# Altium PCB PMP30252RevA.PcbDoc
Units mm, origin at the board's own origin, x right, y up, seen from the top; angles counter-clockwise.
Board outline 62.23 x 46.99 mm, 2 copper layers (Top Layer, Bottom Layer), stack 1.575 mm thick; 70 components, 32 nets, 163 pads, 35 vias.
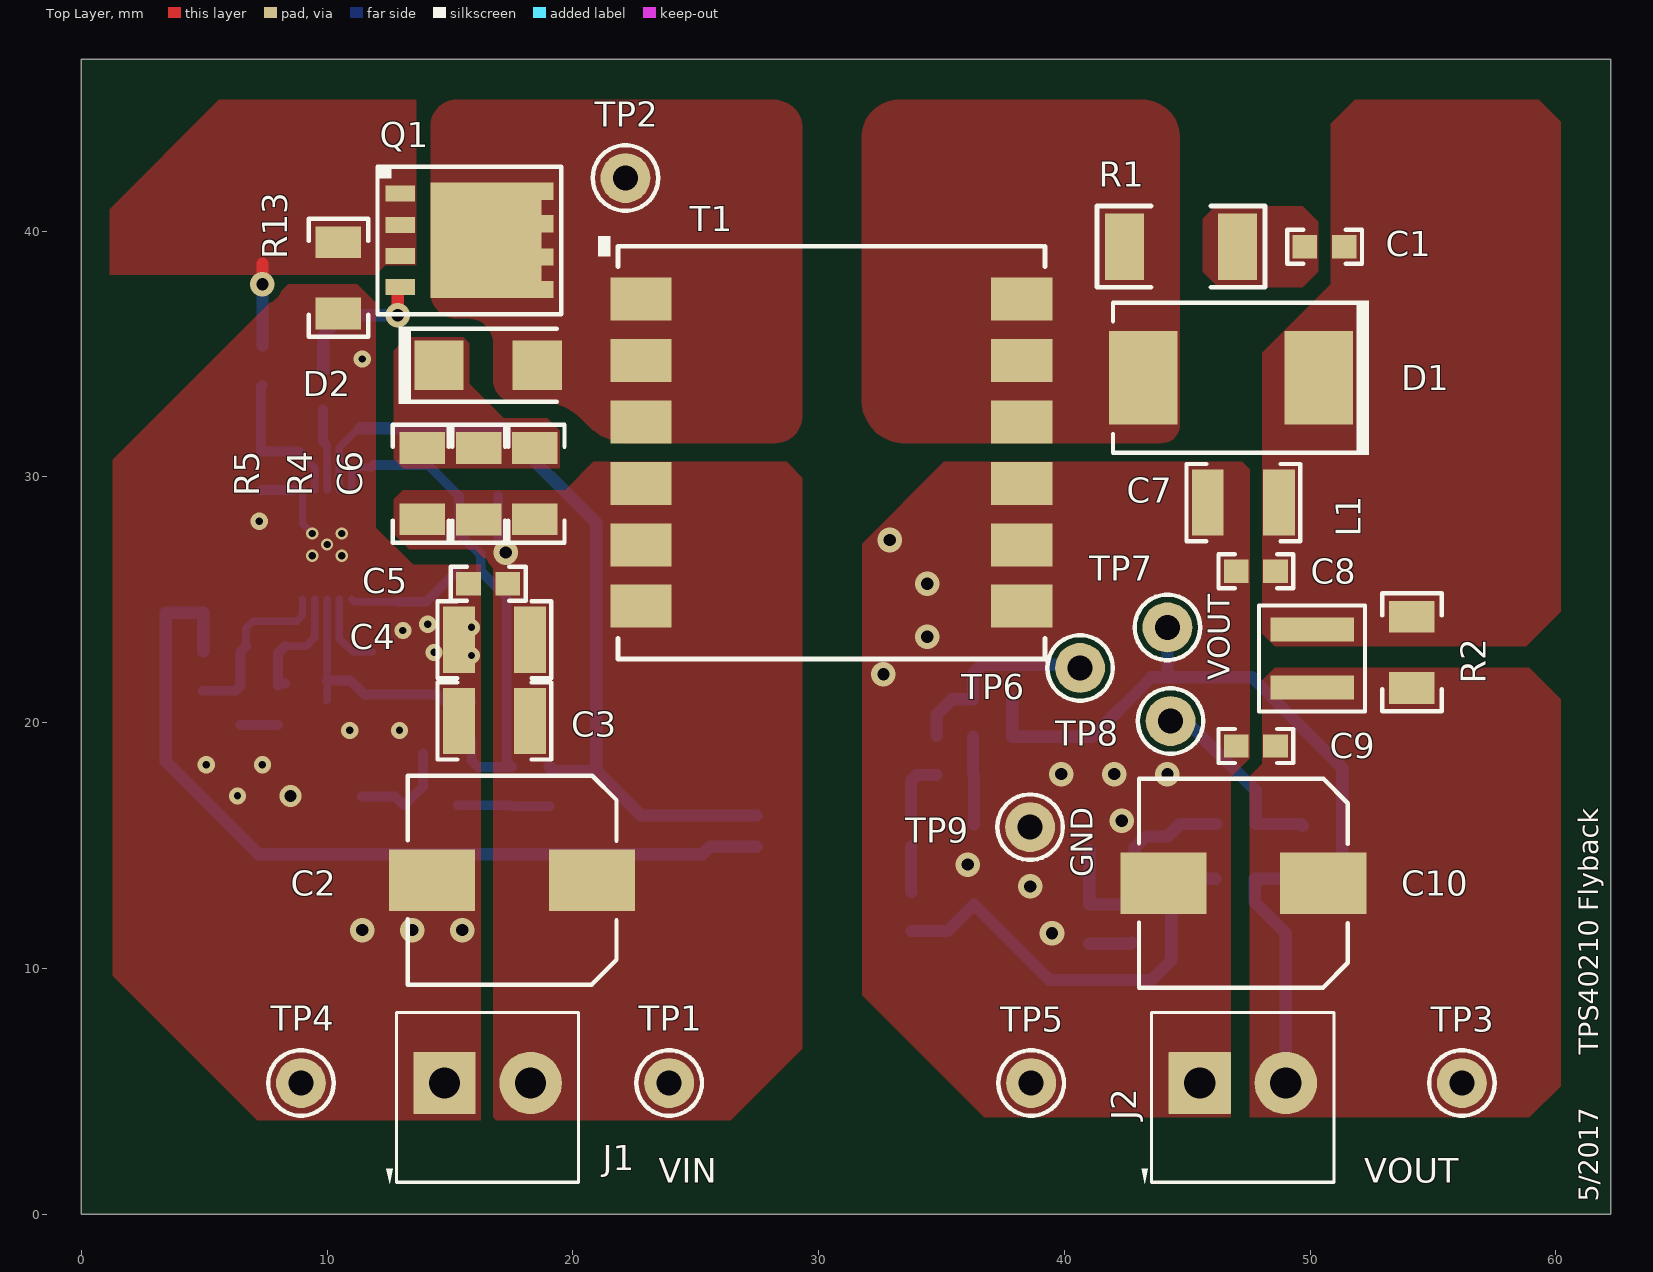
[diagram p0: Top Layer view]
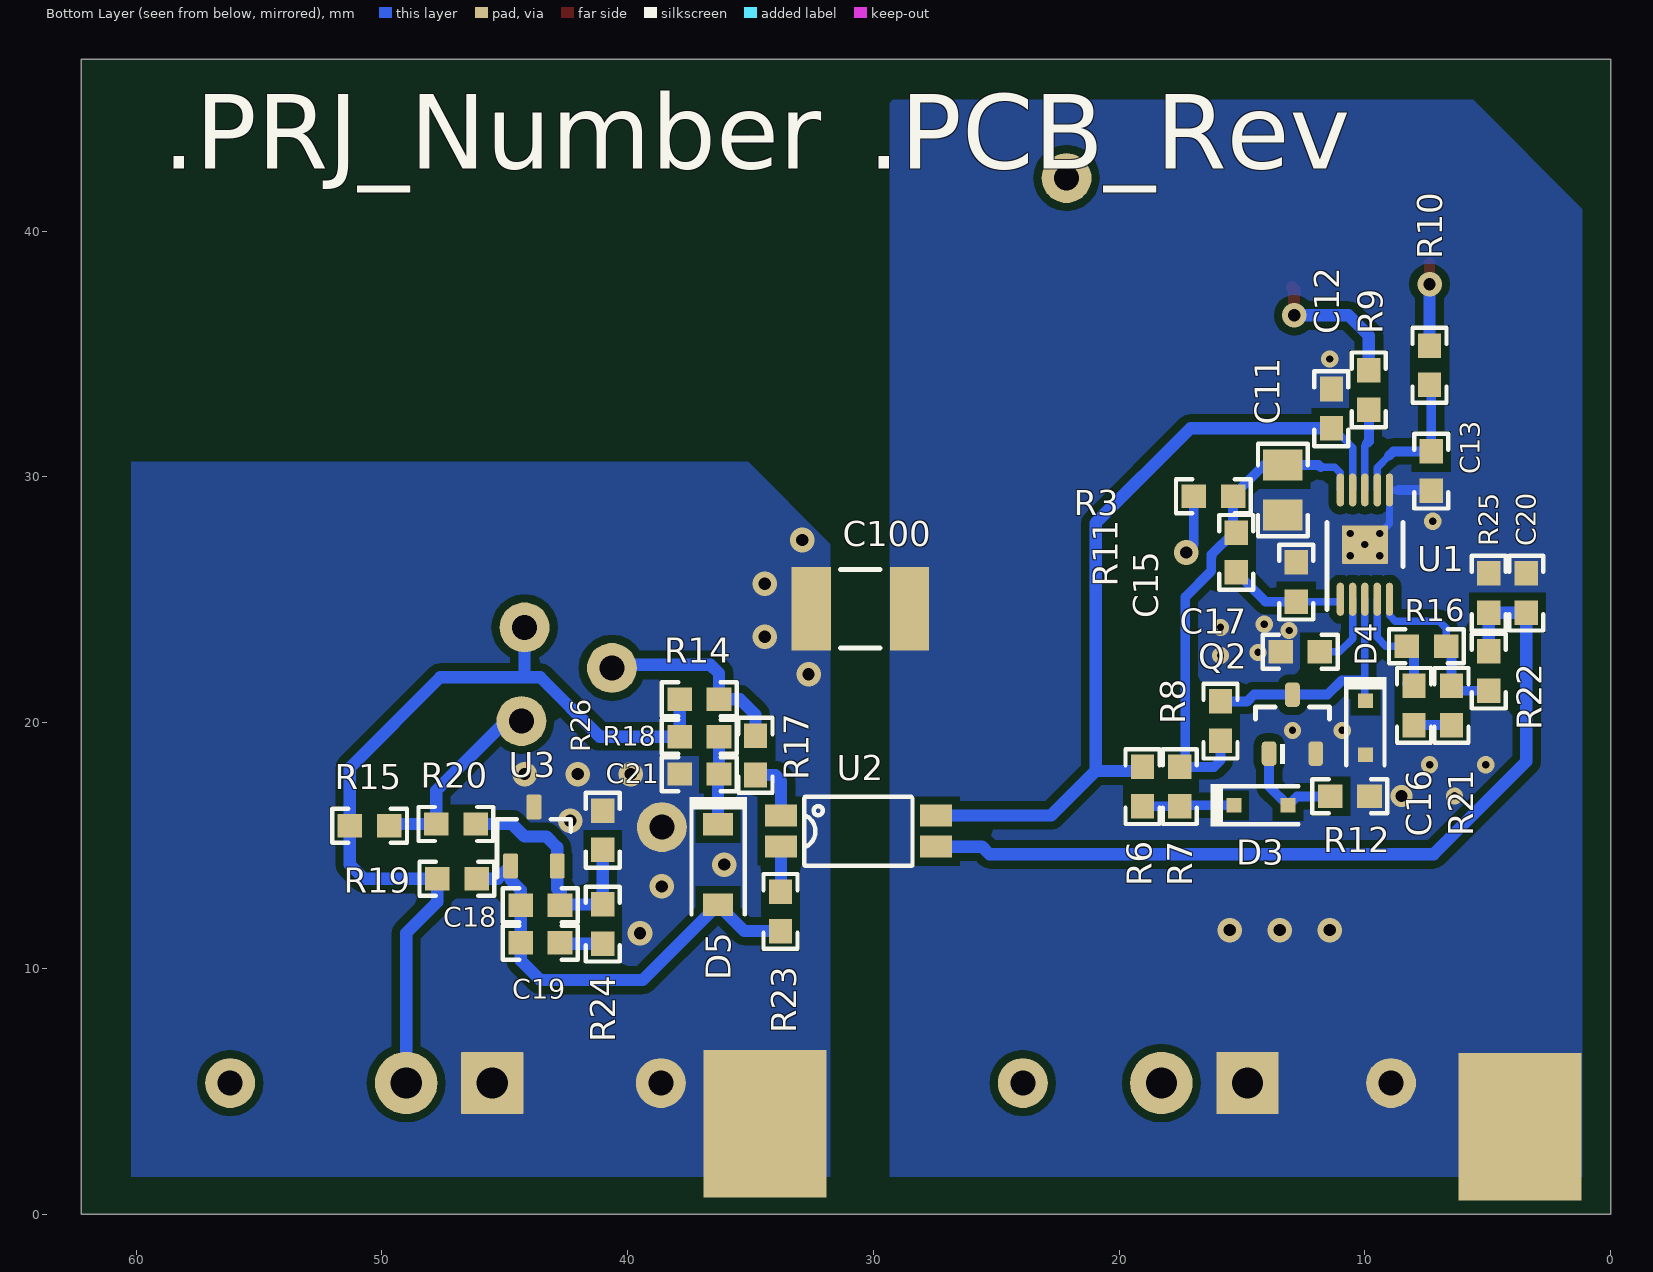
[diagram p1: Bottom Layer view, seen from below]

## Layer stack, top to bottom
Top Solder: solder mask 0.0102, Solder Resist, Dk 3.5
Top Layer: signal copper 0.0356
Dielectric1: core 1.5037, FR-4, Dk 4.8
Bottom Layer: signal copper 0.0356
Bottom Solder: solder mask 0.0102, Solder Resist, Dk 3.5

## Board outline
0,0 62.23,0 62.23,46.99 0,46.99

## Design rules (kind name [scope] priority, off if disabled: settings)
AcuteAngle [All] p1: minimum=4.50000000000000E+0001 checktracksonly=FALSE
AssemblyTestPointUsage [All] p1: valid=2
BoardOutlineClearance BoardOutlineClearance_MountingHoles [OnCopper and InComponentClass('Mounting Holes')] p1: gap=1.016
BoardOutlineClearance BoardOutlineClearance_Poly [OnCopper and InPoly] p2: gap=0.635
BoardOutlineClearance [OnCopper and Not InComponentClass('Logo') and not InComponentClass('FiducialMark') and not InRegion(1000,500,4000,800)] p3: gap=0.5
Clearance Clearance_Keepouts [((IsTrack Or IsArc) And Not InPoly) And IsFree and IsKeepOut vs ((IsTrack Or IsArc) And Not InPoly) And IsFree and IsKeepOut] p1: gap=0
Clearance Clearance_Poly [InPolygon] p2: gap=0.32
Clearance [All] p3: gap=0.32
ComponentClearance ComponentClearance_MountingHoles_FiducialMarks [InComponentClass('Mounting Holes') vs InComponentClass('FiducialMark')] p1: gap=1.27 collisioncheckmode=3 verticalgap=0.254 showdistances=FALSE
ComponentClearance ComponentClearance_Shunt [InComponentClass('Header') vs InComponentClass('Shunt')] p2: gap=0 collisioncheckmode=3 verticalgap=0 showdistances=FALSE
ComponentClearance ComponentClearance_Logo [InComponentClass('Logo')] p3: gap=1.27 collisioncheckmode=3 verticalgap=0.254 showdistances=FALSE
ComponentClearance ComponentClearance_ScrewToNut [(HasFootprint('NY PMS 440 0025 PH')) vs (HasFootprint('Keystone_1902C'))] p4: gap=0.127 collisioncheckmode=3 verticalgap=0.254 showdistances=FALSE
ComponentClearance ComponentClearance_MountingHoles [InComponentClass('Mounting Holes')] p5: gap=6.35 collisioncheckmode=3 verticalgap=2540 showdistances=FALSE
ComponentClearance ComponentClearance_SmallPassives [HasFootprint('0201*') or HasFootprint('0402*') or HasFootprint('0508') or HasFootprint('0603*') or HasFootprint('0612') or HasFootprint('0805*') or HasFootprint('0815*') or HasFootprint('0830*') or HasFootprint('1206*') or HasFootprint('1210*') or HasFootprint('1808*') or HasFootprint('1812*') or HasFootprint('1825*') or HasFootprint('2010*') or HasFootprint('2220*') or HasFootprint('2225*') or HasFootprint('2512*') or HasFootprint('2728*') or HasFootprint('3518*') vs HasFootprint('0201*') or HasFootprint('0402*') or HasFootprint('0508') or HasFootprint('0603*') or HasFootprint('0612') or HasFootprint('0805*') or HasFootprint('0815*') or HasFootprint('0830*') or HasFootprint('1206*') or HasFootprint('1210*') or HasFootprint('1808*') or HasFootprint('1812*') or HasFootprint('1825*') or HasFootprint('2010*') or HasFootprint('2220*') or HasFootprint('2225*') or HasFootprint('2512*') or HasFootprint('2728*') or HasFootprint('3518*')] p6: gap=0.38 collisioncheckmode=3 verticalgap=0.254 showdistances=FALSE
ComponentClearance ComponentClearance_THtoSMT [IsThruComponent vs IsSMTComponent] p7: gap=1.016 collisioncheckmode=3 verticalgap=0.762 showdistances=FALSE
ComponentClearance ComponentClearance_THtoTH [IsThruComponent vs IsThruComponent] p8: gap=0.762 collisioncheckmode=3 verticalgap=0.762 showdistances=FALSE
ComponentClearance [All] p9: gap=0.762 collisioncheckmode=3 verticalgap=0.254 showdistances=FALSE
DiffPairsRouting [All] p1: maxlimit=2.54 minlimit=0.254 mostfreqgap=0.254 toplayer_minwidth=0.381 toplayer_maxwidth=0.381 toplayer_prefwidth=0.381 bottomlayer_minwidth=0.381 bottomlayer_maxwidth=0.381 bottomlayer_prefwidth=0.381 maxuncoupledlength=25.4
FabricationTestPointUsage TestPointUsage [All] p1: valid=2 allowmultiple=FALSE
FabricationTestpoint Testpoint [All] p1: side=3 testpointundercomponent=TRUE minsize=1.016 maxsize=2.54 preferedsize=1.524 minholesize=0 maxholesize=1.016 preferedholesize=0.813 testpointgrid=0.025 allowsidetop=TRUE allowsidebottom=TRUE usegrid=TRUE gridtolerance=0
FanoutControl Fanout_LCC [IsLCC] p1: bgadir=Out bgaviamode=Centered fanoutstyle=Auto fanoutdirection=Alternating viagrid=0.025 // Fanout_LCC (Default Rule)
FanoutControl Fanout_BGA [IsBGA] p2: bgadir=Out bgaviamode=Centered fanoutstyle=Auto fanoutdirection=Alternating viagrid=0.025 // Fanout_BGA (Default Rule)
FanoutControl Fanout_Default [All] p4: bgadir=Out bgaviamode=Centered fanoutstyle=Auto fanoutdirection=Alternating viagrid=0.025 // Fanout_Default (Default Rule)
FanoutControl Fanout_Small [(CompPinCount < 5)] p5: bgadir=Out bgaviamode=Centered fanoutstyle=Auto fanoutdirection=OutThenIn viagrid=0.025 // Fanout_Small (Default Rule)
HoleSize [All] p1: absolutevalues=TRUE maxlimit=6.375 minlimit=0.3 maxpercent=80.000 minpercent=20.000
MinimumAnnularRing MinimumAnnularRing_ThermalPadVias [IsVia and InAnyComponent] p1: minimumring=0.15
MinimumAnnularRing [All] p2: minimumring=0.2
MinimumSolderMaskSliver MinimumSolderMaskSliver_Logo [InComponentClass('Logo') vs InComponentClass('Logo')] p1: minsoldermaskwidth=0.018
MinimumSolderMaskSliver [All] p2: minsoldermaskwidth=0.1
PlaneConnect [All] p1: planeconnectstyle=Relief reliefexpansion=0.254 reliefentries=4 reliefconductorwidth=0.254 reliefairgap=0.254
PolygonConnect [All] p1: connectstyle=Direct reliefconductorwidth=0.254 reliefentries=4 polygonreliefangle="90 Angle" airgapwidth=0.254
RoutingVias ThermalPadVias [IsVia and InAnyComponent] p1: holewidth=0.3 width=0.7 viastyle="Through Hole" minholewidth=0.3 minwidth=0.6 maxholewidth=0.5 maxwidth=1
RoutingVias [All] p2: holewidth=0.5 width=0.9 viastyle="Through Hole" minholewidth=0.3 minwidth=0.6 maxholewidth=1 maxwidth=1.8
SilkToBoardRegionClearance [Not ((IsComment or IsDesignator) And (Hide <> 'False')) and not InRegion(1000,500,4000,800)] p1:
SilkToSilkClearance SilkToSilkClearance_Pb-FreeLogo [(HasFootprint('Pb-Free_Overlay_Medium') OR HasFootprint('Pb-Free_Overlay_Small')) vs (HasFootprint('Pb-Free_Overlay_Medium') OR HasFootprint('Pb-Free_Overlay_Small'))] p1: silktosilkclearance=0
SilkToSilkClearance [All] p2: silktosilkclearance=0.102
SilkToSolderMaskClearance SilkToComponentPadClearance [IsPad and InAnycomponent] p1: minsilkscreentomaskgap=0.127 clearancetoexposedcopper=TRUE
SilkToSolderMaskClearance "Silk to Solder Mask Opening" [All] p2: minsilkscreentomaskgap=0.102 clearancetoexposedcopper=FALSE
SolderMaskExpansion [All] p1: expansion=0.05
Width [All] p1: maxlimit=2.54 minlimit=0.152 preferedwidth=0.254 checkconnectedcopper=TRUE
15 further rules are at their usual default settings.

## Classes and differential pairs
net class U3_Nets: GND2 NetC18_1 NetC18_2
net class U2_Nets: NetC20_1 NetR17_1 NetR23_2 VBP
net class U1_Nets: GND NetC11_1 NetC13_1 NetC15_1 NetC16_1 NetC17_1 NetD4_1 NetR9_1 NetR16_1 VBP
net class TP9_Nets: GND2
net class TP8_Nets: NetR15_2
net class TP7_Nets: VOUT
net class TP6_Nets: NetR14_1
net class TP5_Nets: GND2
net class TP4_Nets: GND
net class TP3_Nets: VOUT
net class TP2_Nets: NetD2_2
net class TP1_Nets: NetC2_1
net class T1_Nets: GND2 NetC2_1 NetD1_2 NetD2_2
net class R26_Nets: GND2 NetC18_1
net class R25_Nets: GND NetC20_1
net class R24_Nets: NetC18_1 NetC19_1
net class R23_Nets: NetC18_2 NetR23_2
net class R22_Nets: NetC20_1 NetR16_1
net class R21_Nets: NetC16_2 NetR16_1
net class R20_Nets: NetC18_1 NetR15_2
net class R19_Nets: NetC18_2 VOUT
net class R18_Nets: NetC21_1 VOUT
net class R17_Nets: NetR14_1 NetR17_1
net class R16_Nets: NetC16_1 NetR16_1
net class R15_Nets: NetR15_2 VOUT
net class R14_Nets: NetR14_1 VOUT
net class R13_Nets: GND NetQ1_1
net class R12_Nets: GND NetD3_2
net class R11_Nets: NetC11_1 NetC15_1
net class R10_Nets: NetC13_1 NetQ1_1
net class R9_Nets: NetQ1_4 NetR9_1
net class R8_Nets: NetC11_1 NetD4_1
net class R7_Nets: NetC11_1 NetD3_1
net class R6_Nets: NetD3_1 VBP
net class R5_Nets: NetC2_1 NetC6_2
net class R4_Nets: NetC2_1 NetC6_2
net class R3_Nets: NetC2_1 NetC11_1
net class R2_Nets: NetC1_1 VOUT
net class R1_Nets: NetC1_2 NetD1_2
net class Q2_Nets: GND NetD3_2 NetD4_1
net class Q1_Nets: NetD2_2 NetQ1_1 NetQ1_4
net class L1_Nets: NetC1_1 VOUT
net class J2_Nets: GND2 VOUT
net class J1_Nets: GND NetC2_1
net class D5_Nets: NetC18_2 NetC21_1
net class D4_Nets: GND NetD4_1
net class D3_Nets: NetD3_1 NetD3_2
net class D2_Nets: NetC6_2 NetD2_2
net class D1_Nets: NetC1_1 NetD1_2
net class C100_Nets: GND GND2
net class C21_Nets: GND2 NetC21_1
net class C20_Nets: GND NetC20_1
net class C19_Nets: NetC18_2 NetC19_1
net class C18_Nets: NetC18_1 NetC18_2
net class C17_Nets: GND NetC17_1
net class C16_Nets: NetC16_1 NetC16_2
net class C15_Nets: GND NetC15_1
net class C13_Nets: GND NetC13_1
net class C12_Nets: GND VBP
net class C11_Nets: GND NetC11_1
net class C10_Nets: GND2 VOUT
net class C9_Nets: GND2 VOUT
net class C8_Nets: GND2 NetC1_1
net class C7_Nets: GND2 NetC1_1
net class C6_Nets: NetC2_1 NetC6_2
net class C5_Nets: GND NetC2_1
net class C4_Nets: GND NetC2_1
net class C3_Nets: GND NetC2_1
net class C2_Nets: GND NetC2_1
net class C1_Nets: NetC1_1 NetC1_2

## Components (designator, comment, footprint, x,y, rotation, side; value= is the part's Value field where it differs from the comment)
C1 "GRM188R72A222KA01D" 0603 50.589,39.37 r180 top
C2 "EEHZC1H680P" SM_RADIAL_8MM 17.526,13.589 r180 top
C3 "GRM32ER71H106KA12L" 1210_270 16.807,20.066 r180 top
C4 "GRM32ER71H106KA12L" 1210_270 16.807,23.368 r180 top
C5 "GCM188R71H104KA57D" 0603 16.553,25.654 r180 top
C6 "GRM319R72A104KA01D" 1206 18.448,29.726 r90 top
C7 "GRM32ER71E226KE15L" 1210_270 47.287,28.956 r180 top
C8 "GCM188R71H104KA57D" 0603 47.795,26.162 r180 top
C9 "GCM188R71H104KA57D" 0603 47.795,19.05 r180 top
C10 "EEHZC1E221P" SM_RADIAL_8MM 47.287,13.462 r180 top
C11 "GRM219R71H334KA88D" 0805_HV 13.335,29.464 r270 bottom
C12 "GRM188R71C105KA12D" 0603 11.36,32.777 r90 bottom
C13 "GRM188R71H221KA01D" 0603 7.296,30.237 r270 bottom
C15 "GRM1885C1H471JA01D" 0603 12.792,25.723 r90 bottom
C16 "GRM188R71H103KA01D" 0603 8.001,20.701 r270 bottom
C17 "GCM188R71H104KA57D" 0603 12.63,22.879 r0 bottom
C18 "GRM1885C1H330JA01D" 0603 43.553,12.565 r0 bottom
C19 "GRM188R71H102KA01D" 0603 43.553,11.041 r0 bottom
C20 "GRM188R71H332KA01D" 0603 3.429,25.273 r90 bottom
C21 "GRM188R71C105KA12D" 0603 37.084,17.907 r0 bottom
C100 "1812GC472KA1" 1812 30.531,24.638 r180 bottom
D1 "B380-13-F" SMC 46.779,34.036 r180 top
D2 "ES1B-13-F" SMA 16.553,34.544 r0 top
D3 "MMSZ5237BS-7-F" SOD-323 14.224,16.637 r180 bottom
D4 "MMSZ5235BS-7-F" sod-323 9.976,19.793 r270 bottom
D5 "MMSD914" SOD-123 36.322,14.224 r270 bottom
J1 "ED555/2DS" TERM_BLK_ED555-2DS 14.775,5.334 r0 top
J2 "ED555/2DS" TERM_BLK_ED555-2DS 45.509,5.334 r0 top
L1 "XFL4020-332MEB" XFL4020 50.081,22.606 r270 top
Q1 "BSC340N08NS3 G" PG-TDSON-8 15.791,39.624 r0 top
Q2 "MMBT2222A" SOT-23 12.946,19.939 r90 bottom
R1 "CRCW201022R0JNEF" 2010 44.747,39.37 r0 top
R2 "CRCW12065R60JNEA" 1206 54.145,22.86 r270 top
R3 "CRCW060310R0FKEA" 0603 16.162,29.218 r0 bottom
R4 "CRCW120639K0JNEA" 1206 16.162,29.718 r270 top
R5 "CRCW120639K0JNEA" 1206 13.876,29.726 r270 top
R6 "CRCW0603100KFKEA" 0603 19.05,17.399 r90 bottom
R7 "CRCW060340K2FKEA" 0603 17.526,17.399 r90 bottom
R8 "CRCW060340K2FKEA" 0603 15.875,20.066 r270 bottom
R9 "CRCW06033R32FKEA" 0603 9.836,33.539 r90 bottom
R10 "CRCW06031K00FKEA" 0603 7.366,34.544 r90 bottom
R11 "CRCW0603287KFKEA" 0603 15.24,26.924 r90 bottom
R12 "CRCW0603100KFKEA" 0603 10.611,16.999 r0 bottom
R13 "WSLP1206R0150FEA" 1206 10.457,38.1 r90 top
R14 "CRCW060349R9FKEA" 0603 37.084,20.955 r0 bottom
R15 "CRCW060349R9FKEA" 0603 50.505,15.806 r180 bottom
R16 "CRCW060330K1FKEA" 0603 7.493,23.114 r0 bottom
R17 "CRCW06032K00FKEA" 0603 34.798,18.669 r90 bottom
R18 "CRCW060320K0FKEA" 0603 37.084,19.431 r0 bottom
R19 "CRCW06032K00FKEA" 0603 46.949,13.647 r0 bottom
R20 "CRCW060320K0FKEA" 0603 46.99,15.875 r0 bottom
R21 "CRCW06035K11FKEA" 0603 6.477,20.701 r270 bottom
R22 "CRCW060310K0FKEA" 0603 4.953,22.098 r90 bottom
R23 "CRCW06030000Z0EA" 0603 33.782,12.319 r90 bottom
R24 "CRCW060340K2FKEA" 0603 41.013,11.803 r270 bottom
R25 "CRCW06031K00FKEA" 0603 4.953,25.273 r270 bottom
R26 "CRCW06035K23FKEA" 0603 41.021,15.621 r270 bottom
T1 "749196241" WURTH_749196211 30.523,30.988 r0 top
TP1 "5000" Keystone5000 23.919,5.334 r180 top
TP2 "5002" Keystone5002 22.141,42.164 r90 top
TP3 "5000" Keystone5000 56.177,5.334 r90 top
TP4 "5001" Keystone5001 8.933,5.334 r180 top
TP5 "5001" Keystone5001 38.651,5.334 r90 top
TP6 "5003" Keystone5003 40.64,22.225 r90 top
TP7 "5000" Keystone5000 44.196,23.876 r90 top
TP8 "5003" Keystone5003 44.323,20.066 r90 top
TP9 "5001" Keystone5001 38.608,15.748 r90 top
U1 "TPS40210" DGQ0010D_N 9.998,27.247 r90 bottom
U2 "TCMT1107" SOP-4 30.607,15.588 r180 bottom
U3 "TL431" DBZ0003A_N 43.815,15.367 r90 bottom

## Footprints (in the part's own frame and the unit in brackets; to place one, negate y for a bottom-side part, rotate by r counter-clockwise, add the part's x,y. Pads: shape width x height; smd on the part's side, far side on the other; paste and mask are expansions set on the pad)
0603 [mm] "0603 from SM-752 data"
  rect 1x0.95 smd: 1(-0.8,0) 2(0.8,0)
  silkscreen extent -1.52,-0.69 1.52,0.69, body extent -0.87,-0.47 0.87,0.47, height 1
0805_HV [mil] "0805 with 30mil clearance between pads"
  rect 50x63 smd: 1(-40,0) 2(40,0)
  silkscreen extent -74,-40 74,40, body extent -43,-29 43,29, height 57
1206 [mm] "1206 from SM-752 data"
  rect 1.3x1.85 smd: 1(-1.45,0) 2(1.45,0)
  silkscreen extent -2.4,-1.21 2.4,1.21, body extent -1.7,-0.9 1.7,0.9, height 1.35
1210_270 [mm] "1210"
  rect 1.3x2.7 smd: 1(-1.45,0) 2(1.45,0)
  silkscreen extent -2.32,-1.57 2.32,1.57, body extent -1.7,-1.35 1.7,1.35, height 2.7
1812 [mm]
  rect 1.6x3.4 smd: 1(-2,0) 2(2,0)
  silkscreen extent -0.8,-1.6 0.8,1.6, body extent -2.4,-1.7 2.4,1.7, height 1.35
2010 [mm] "Chip Capacitor, Body 5.08x2.54mm, IPC Medium Density"
  rect 1.6x2.7 smd: 1(-2.3,0) 2(2.3,0)
  silkscreen extent -3.42,-1.65 3.42,1.65, body extent -2.73,-1.45 2.73,1.45, height 1.66
DBZ0003A_N [mm] "SOT23, 3-Leads, Body 2.9x1.3mm, Pitch 0.95mm, Lead Span 2.4mm, IPC Medium Density"
  rrect17% 1x0.6 smd: 1(-1.2,0.95) 2(-1.2,-0.95) 3(1.2,0)
  silkscreen extent -1.65,-1.5 0.7,1.5, body extent -1.26,-1.46 1.26,1.46, height 0.98
DGQ0010D_N [mm] "TSSOP, 10-Leads, Body 3x3mm, Pitch 0.5mm, Thermal Pad 1.88x1.57mm, IPC Medium Density"
  rrect100% 1.35x0.3 smd: 1(-2.225,1) 2(-2.225,0.5) 3(-2.225,0) 4(-2.225,-0.5) 5(-2.225,-1) 6(2.225,-1) 7(2.225,-0.5) 8(2.225,0) 9(2.225,0.5) 10(2.225,1)
  rrect6% 1.57x1.88 smd: 11(0,0)
  silkscreen extent -2.65,-1.55 0.9,1.55, body extent -2.46,-1.5 2.46,1.5, height 1.1
Keystone5000 [mil] "For Keystone 500x miniature loop terminals"
  round 80 hole 40: 1(0,0)
  silkscreen extent -52,-52 52,52, body extent -49,-49 49,49, height 182
Keystone5001 [mil] "For Keystone 500x miniature loop terminals"
  round 80 hole 40: 1(0,0)
  silkscreen extent -52,-52 52,52, body extent -49,-49 49,49, height 182
Keystone5002 [mil] "For Keystone 500x miniature loop terminals"
  round 80 hole 40: 1(0,0)
  silkscreen extent -52,-52 52,52, body extent -49,-49 49,49, height 182
Keystone5003 [mil] "For Keystone 500x miniature loop terminals"
  round 80 hole 40: 1(0,0)
  silkscreen extent -52,-52 52,52, body extent -49,-49 49,49, height 182
PG-TDSON-8 [mm] "Infineon recommended land pattern"
  rect 1.2x0.65 smd: 1(-2.825,1.905) 2(-2.825,0.635) 3(-2.825,-0.635) 4(-2.825,-1.905)
  rect 0.5x0.7 smd: 5(3.175,-2) 6(3.175,-0.675) 7(3.175,0.675) 8(3.175,2)
  rect 4.5x4.7 smd paste-2.25: 9(0.675,0)
  silkscreen extent -3.74,-3 3.74,3, body extent -3.17,-2.89 3.17,2.9, height 1.1
SM_RADIAL_8MM [mm] "Nichicon 8x10"
  rect 3.5x2.5 smd: 1(-3.25,0) 2(3.25,0)
  silkscreen extent -4.25,-4.25 4.25,4.25, body extent -4.25,-4.25 4.25,4.25, height 10.5
SMA [mm] "Molded Diode, 2-Leads, Body 4.3x2.6mm, IPC Medium Density, based on OnSemi component dimensions and land pattern"
  rect 2x2 smd: 1(-2,0) 2(2,0)
  silkscreen extent -3.66,-1.57 2.79,1.57, body extent -2.6,-1.3 2.6,1.3, height 2.42
SMC [mil] "Molded Diode, 2-Leads, Body 6.9x5.8mm, IPC Medium Density, based on OnSemi component dimensions and land patterns"
  rect 110x150 smd: 1(-140.49,0) 2(140.49,0)
  silkscreen extent -221,-124 189,123, body extent -156,-116 156,116, height 91
SOD-123 [mm] "On Semi recommended land pattern"
  rect 0.915x1.22 smd: 1(-1.637,0) 2(1.637,0)
  silkscreen extent -2.74,-1.17 2.03,1.17, body extent -1.93,-0.9 1.93,0.9, height 1.35
SOD-323 [mm] "NXP recommended land pattern"
  rect 0.6x0.6 smd paste-0.05: 1(-1.1,0) 2(1.1,0)
  silkscreen extent -2.06,-0.86 1.53,0.86, body extent -1.3,-0.67 1.3,0.68, height 1.1
sod-323 [mm] "NXP recommended land pattern"
  rect 0.6x0.6 smd paste-0.05: 1(-1.1,0) 2(1.1,0)
  silkscreen extent -2.06,-0.86 1.53,0.86, body extent -1.3,-0.67 1.3,0.68, height 1.1
SOP-4 [mm] "Vishay Half Pitch Mini-Flat Package"
  rect 1.3x0.9 smd: 1(-3.15,0.635) 2(-3.15,-0.635) 3(3.15,-0.635) 4(3.15,0.635)
  silkscreen extent -2.2,-1.41 2.2,1.39, body extent -3.5,-1.4 3.5,1.4, height 2.12
SOT-23 [mm] "SOT23, 3-Leads, Body 2.9x1.3mm, Pitch 0.95mm, Lead Span 2.5mm, IPC Medium Density"
  rrect50% 1x0.6 smd: 1(-1.2,0.95) 2(-1.2,-0.95) 3(1.2,0)
  silkscreen extent -1.62,-1.5 0.7,1.5, body extent -1.16,-1.45 1.21,1.45, height 1
TERM_BLK_ED555-2DS [mil]
  rrect4% 100x100 hole 50: 1(0,0)
  round 100 hole 50: 2(138,0)
  silkscreen extent -93,-161 215,113, body extent -69,-150 207,106, height 323
WURTH_749196211 [mm] "Wurth"
  rect 2.5x1.75 smd: 1(-7.75,6.25) 2(-7.75,3.75) 3(-7.75,1.25) 4(-7.75,-1.25) 5(-7.75,-3.75) 6(-7.75,-6.25) 7(7.75,-6.25) 8(7.75,-3.75) 9(7.75,-1.25) 10(7.75,1.25) 11(7.75,3.75) 12(7.75,6.25)
  silkscreen extent -9.5,-8.4 8.69,8.8, body extent -8.4,-8.15 8.4,8.15, height 7.42
XFL4020 [mm] "Coilcraft XFL4020 7/18/12"
  rect 0.98x3.4 smd: 1(-1.181,0) 2(1.181,0)
  silkscreen extent -2.16,-2.16 2.16,2.16, body extent -2.15,-2.15 2.15,2.15, height 2.1

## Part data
C1: "CAP, CERM, 2200 pF, 100 V, +/- 10%, X7R, 0603"
C2: "CAP, Polymer Hybrid, 68 µF, 50 V, +/- 20%, 30 ohm, 8x10 SMD"
C3 C4: "CAP, CERM, 10 µF, 50 V, +/- 10%, X7R, 1210"
C5 C8 C9 C17: "CAP, CERM, 0.1 µF, 50 V, +/- 10%, X7R, 0603"
C6: "CAP, CERM, 0.1 µF, 100 V, +/- 10%, X7R, 1206"
C7: "CAP, CERM, 22 µF, 25 V, +/- 10%, X7R, 1210"
C10: "CAP, Polymer Hybrid, 220 µF, 25 V, +/- 20%, 27 ohm, 8x10 SMD"
C11: "CAP, CERM, 0.33 µF, 50 V, +/- 10%, X7R, 0805"
C12 C21: "CAP, CERM, 1 µF, 16 V, +/- 10%, X7R, 0603"
C13: "CAP, CERM, 220 pF, 50 V, +/- 10%, X7R, 0603"
C15: "CAP, CERM, 470 pF, 50 V, +/- 5%, C0G/NP0, 0603"
C16: "CAP, CERM, 0.01 µF, 50 V, +/- 10%, X7R, 0603"
C18: "CAP, CERM, 33 pF, 50 V, +/- 5%, C0G/NP0, 0603"
C19: "CAP, CERM, 1000 pF, 50 V, +/- 10%, X7R, 0603"
C20: "CAP, CERM, 3300 pF, 50 V, +/- 10%, X7R, 0603"
C100: "CAP, CERM, 4700 pF, 2000 V, +/- 10%, X7R, 1812"
D1: "Diode, Schottky, 80 V, 3 A, SMC"
D2: "Diode, Superfast Rectifier, 100 V, 1 A, SMA"
D3: "Diode, Zener, 8.2 V, 200 mW, SOD-323"
D4: "Diode, Zener, 6.8V, 200mW, SOD-323"
D5: library part MMSD914T1G, "Diode, Switching, 100 V, 0.2 A, SOD-123"
J1 J2: "Terminal Block, 6A, 3.5mm Pitch, 2-Pos, TH"
L1: "Inductor, Shielded, Composite, 3.3 µH, 2.9 A, 0.03 ohm, SMD"
Q1: "MOSFET, N-CH, 80 V, 23 A, PG-TDSON-8"
Q2: library part "MMBT2222A, Fairchild Semiconductor", "Transistor, NPN, 40V, 0.15A, SOT-23"
R1: "RES, 22, 5%, 0.75 W, AEC-Q200 Grade 0, 2010"
R2: "RES, 5.6, 5%, 0.25 W, 1206"
R3: "RES, 10.0, 1%, 0.1 W, 0603"
R4 R5: "RES, 39 k, 5%, 0.25 W, 1206"
R6 R12: "RES, 100k ohm, 1%, 0.1W, 0603"
R7 R8 R24: "RES, 40.2 k, 1%, 0.1 W, 0603"
R9: "RES, 3.32, 1%, 0.1 W, 0603"
R10 R25: "RES, 1.00 k, 1%, 0.1 W, 0603"
R11: "RES, 287 k, 1%, 0.1 W, 0603"
R13: "RES, 0.015, 1%, 1 W, 1206"
R14 R15: "RES, 49.9, 1%, 0.1 W, 0603"
R16: "RES, 30.1 k, 1%, 0.1 W, 0603"
R17 R19: "RES, 2.00 k, 1%, 0.1 W, 0603"
R18 R20: "RES, 20.0 k, 1%, 0.1 W, 0603"
R21: "RES, 5.11 k, 1%, 0.1 W, 0603"
R22: "RES, 10.0 k, 1%, 0.1 W, 0603"
R23: "RES, 0, 5%, 0.1 W, 0603"
R26: "RES, 5.23 k, 1%, 0.1 W, 0603"
T1: library part 749196211, "Transformer, 6.6uH, SMT"
TP1 TP3 TP7: "Test Point, Miniature, Red, TH"
TP2: "Test Point, Miniature, White, TH"
TP4 TP5 TP9: "Test Point, Miniature, Black, TH"
TP6 TP8: "Test Point, Miniature, Orange, TH"
U1: library part TPS40210QDGQRQ1, "4.5-V TO 52-V INPUT CURRENT MODE BOOST CONTROLLER, DGQ0010D"
U2: "Optocoupler, 3.75 kV, 80-160% CTR, SMT"
U3: library part TL431AIDBZR, "Adjustable Precision Shunt Regulator, 34 ppm / degC, 100 mA, -40 to 85 degC, 3-pin SOT-23 (DBZ), Green (RoHS & no Sb/Br)"

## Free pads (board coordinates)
  rect 5x6 smd far side: 2(34.417,3.683) 3(3.683,3.556)

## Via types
v1: diameter 1, hole 0.5, Top Layer to Bottom Layer, 11 vias
v2: diameter 0.7, hole 0.3, Top Layer to Bottom Layer, 8 vias
v3: diameter 1, hole 0.5, Top Layer to Bottom Layer, tented top, 5 vias
v4: diameter 0.5, hole 0.3, Top Layer to Bottom Layer, 5 vias
v5: diameter 0.7, hole 0.3, Top Layer to Bottom Layer, tented bottom, 2 vias
v6: diameter 1, hole 0.5, Top Layer to Bottom Layer, tented bottom, 1 vias
v7: diameter 0.7, hole 0.3, Top Layer to Bottom Layer, tented both sides, 1 vias
v8: diameter 0.7, hole 0.3, Top Layer to Bottom Layer, tented top, 1 vias
v9: diameter 0.9, hole 0.5, Top Layer to Bottom Layer, tented bottom, 1 vias

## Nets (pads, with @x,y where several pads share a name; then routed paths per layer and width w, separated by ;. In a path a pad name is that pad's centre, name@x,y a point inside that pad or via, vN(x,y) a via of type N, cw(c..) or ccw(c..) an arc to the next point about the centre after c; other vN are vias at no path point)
GND: C2.2 C3.2 C4.2 C5.2 C11.2 C12.2 C13.2 C15.2 C17.2 C20.2 C100.2 D4.2 J1.1 pad.3 Q2.2 R12.1 R13.1 R25.1 TP4.1 U1.6 U1.11 | length 3.7
  Bottom Layer w0.3: 8.636,29.464 8.99,29.464 U1.6 8.998,28.097 v4(9.398,27.697)
  Bottom Layer w0.4: C13.2 7.323,29.464 8.636,29.464
  other v1: 11.43,11.557 13.462,11.557 15.494,11.557
  other v2: 5.08,18.288 7.366,18.288 15.875,22.733 14.351,22.86 13.081,23.749 14.097,24.003 7.239,28.194 11.43,34.798
  other v4: 9.398,26.797 10.598,26.797 9.998,27.247 10.598,27.697
  other v5: 6.35,17.018 15.875,23.876
  other v7: 12.946,19.685
  other v8: 10.922,19.685
  other v9: 8.509,17.018
GND2: C7.2 C8.2 C9.2 C10.2 C21.2 C100.1 J2.1 pad.2 R26.1 T1.7 T1.8 T1.9 TP5.1 TP9.1 U3.3
  other v1: 39.497,11.43 36.068,14.224 42.342,16.002 42.037,17.907 44.196,17.907
  other v3: 38.608,13.335 32.639,21.971 34.417,23.495 34.417,25.654 32.893,27.432
  other v6: 39.878,17.907
NetC1_1: C1.1 C7.1 C8.1 D1.1 L1.1 R2.1
NetC1_2: C1.2 R1.2
NetC2_1: C2.1 C3.1 C4.1 C5.1 C6.1 J1.2 R3.2 R4.2 R5.2 T1.4 T1.5 T1.6 TP1.1 | length 2.4
  Bottom Layer w0.4: R3.2 16.962,27.234 v1(17.272,26.924)
NetC6_2: C6.2 D2.1 R4.1 R5.1
NetC11_1: C11.1 R3.1 R7.2 R8.2 R11.2 U1.10 | length 20.4
  Bottom Layer w0.3: U1.10 10.998,30.175 11.22,30.397 11.798,30.397
  Bottom Layer w0.4: 11.798,30.397 11.881,30.48 C11.1 14.1,30.48 R3.1 15.362,27.846 R11.2 15.35,27.724 16.235,26.839 16.235,26.729 16.252,26.712 16.252,26.166 17.307,25.111 17.307,18.418 R7.2 16.142,18.199 15.875,18.466 R8.2
NetC13_1: C13.1 R10.1 U1.7 | length 6.1
  Bottom Layer w0.3: 9.017,30.861 9.498,30.38 U1.7
  Bottom Layer w0.4: R10.1 7.296,33.674 C13.1 8.841,31.037 9.017,30.861
NetC15_1: C15.1 R11.1 U1.1 | length 4.8
  Bottom Layer w0.3: U1.1 11.097,24.923 C15.1
  Bottom Layer w0.4: C15.1 14.039,24.923 R11.1
NetC16_1: C16.1 R16.2 U1.4 | length 4.6
  Bottom Layer w0.3: R16.2 9.144,23.114 9.498,23.468 U1.4
  Bottom Layer w0.4: C16.1 8.001,22.822 R16.2
NetC16_2: C16.2 R21.2 | length 1.5
  Bottom Layer w0.4: R21.2 C16.2
NetC17_1: C17.1 U1.2 | length 3.2
  Bottom Layer w0.3: U1.2 10.498,23.411 11.03,22.879 C17.1
NetC18_1: C18.1 R20.1 R24.1 R26.2 U3.2 | length 10
  Bottom Layer w0.5: R26.2 41.013,14.813 R24.1 42.715,12.603 42.715,13.079 42.865,13.229 U3.2 42.865,14.925 43.307,15.367 44.196,15.367 44.704,15.875 R20.1
NetC18_2: C18.2 C19.2 D5.2 R19.1 R23.1 U3.1 | length 18.2
  Bottom Layer w0.5: R23.1 35.254,11.519 D5.2 39.384,9.525 43.561,9.525 44.353,10.317 C19.2 C18.2 44.353,13.193 44.765,13.605 U3.1 45.285,13.647 R19.1
NetC19_1: C19.1 R24.2 | length 1.8
  Bottom Layer w0.5: R24.2 42.715,11.003 C19.1
NetC20_1: C20.1 R22.2 R25.2 U2.3 | length 34.9
  Bottom Layer w0.5: R22.2 R25.2 C20.1 3.429,18.415 7.201,14.643 25.273,14.643 25.583,14.953 U2.3
NetC21_1: C21.1 D5.1 R18.1 | length 3.6
  Bottom Layer w0.5: R18.1 C21.1 36.322,17.869 D5.1
NetD1_2: D1.2 R1.1 T1.10 T1.11 T1.12
NetD2_2: D2.2 Q1.5 Q1.6 Q1.7 Q1.8 Q1.9 T1.1 T1.2 T1.3 TP2.1
NetD3_1: D3.1 R6.1 R7.1 | length 3.7
  Bottom Layer w0.4: D3.1 17.488,16.637 R7.1 R6.1
NetD3_2: D3.2 Q2.1 R12.2 | length 4.3
  Bottom Layer w0.4: R12.2 12.762,16.999 D3.2 13.896,17.409 Q2.1
NetD4_1: D4.1 Q2.3 R8.1 U1.3 | length 10.4
  Bottom Layer w0.3: D4.1 9.998,20.915 9.998,21.717 U1.3
  Bottom Layer w0.4: 9.998,21.717 10.942,21.717 11.52,21.139 Q2.3 14.512,21.139 14.785,20.866 R8.1
NetQ1_1: Q1.1 Q1.2 Q1.3 R10.2 R13.2 | length 3.3
  Top Layer w0.5: v1(7.366,37.846) 7.366,38.673
  Bottom Layer w0.5: R10.2 v1(7.366,37.846)
NetQ1_4: Q1.4 R9.2 | length 6
  Top Layer w0.5: v1(12.87,36.576) 12.87,37.623 Q1.4
  Bottom Layer w0.5: R9.2 9.836,35.744 10.668,36.576 v1(12.87,36.576)
NetR9_1: R9.1 U1.8 | length 3.3
  Bottom Layer w0.3: 9.906,31.369 9.998,31.277 U1.8
  Bottom Layer w0.4: R9.1 9.836,31.439 9.906,31.369
NetR14_1: R14.1 R17.2 TP6.1 | length 8.2
  Bottom Layer w0.5: R17.2 34.798,20.32 35.433,20.955 R14.1 36.284,22.009 36.627,22.352 40.513,22.352 TP6.1
NetR15_2: R15.2 R20.2 TP8.1 | length 7.9
  Bottom Layer w0.5: TP8.1 44.958,20.066 47.79,17.234 R20.2 49.636,15.875 R15.2
NetR16_1: R16.1 R21.1 R22.1 U1.5 | length 7.2
  Bottom Layer w0.3: R16.1 6.693,23.838 6.985,24.13 8.763,24.13 8.998,24.365 U1.5
  Bottom Layer w0.4: R22.1 6.274,21.298 R21.1 6.477,22.898 R16.1
NetR17_1: R17.1 U2.1 | length 2.5
  Bottom Layer w0.5: U2.1 33.757,17.628 33.998,17.869 R17.1
NetR23_2: R23.2 U2.2 | length 1.8
  Bottom Layer w0.5: U2.2 33.757,13.144 R23.2
VBP: C12.1 R6.2 U1.9 U2.4 | length 33.4
  Bottom Layer w0.3: U1.9 10.498,31.199 11.276,31.977 C12.1
  Bottom Layer w0.5: C12.1 17.096,31.977 20.955,28.118 20.955,18.034 ; R6.2 19.215,18.034 20.955,18.034 ; U2.4 22.766,16.223 20.955,18.034
VOUT: C9.1 C10.1 J2.2 L1.2 R2.2 R14.2 R15.1 R18.2 R19.2 TP3.1 TP7.1 | length 36.1
  Bottom Layer w0.5: R14.2 R18.2 41.148,19.431 43.561,21.844 44.196,21.844 ; TP7.1 44.196,21.844 ; J2.2 49.014,11.438 47.749,12.703 R19.2 50.731,13.647 51.308,14.224 51.308,15.803 R15.1 51.305,18.164 47.625,21.844 44.196,21.844

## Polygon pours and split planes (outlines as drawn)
NetC6_2 on Top Layer "TOP_LAYER_NETC6_2_P006" (solid, remove dead copper, pour order 6): 19.474,30.353 13.082,30.353 12.701,30.734 12.701,35.137 13.251,35.687 15.41,35.687 15.537,35.687 15.791,35.433 15.791,33.782 16.934,32.639 17.188,32.385 18.712,32.385 18.966,32.385 19.474,31.877
GND on Top Layer "TOP_LAYER_GND_P008" (solid, remove dead copper, pour order 8): 16.256,3.81 7.155,3.81 1.27,9.695 1.27,30.691 8.425,37.846 11.219,37.846 11.473,37.592 11.981,37.084 11.981,27.94 13.505,26.416 16.256,26.416
NetQ1_1 on Top Layer "TOP_LAYER_NETQ1_1_P010" (solid, remove dead copper, pour order 10): 1.143,38.227 11.981,38.227 12.362,38.608 13.632,38.608 13.632,45.339 5.588,45.339 1.143,40.894
VOUT on Top Layer "TOP_LAYER_VOUT_P012" (solid, remove dead copper, pour order 12): 47.541,3.937 47.541,17.817 48.049,18.325 48.049,21.717 48.557,22.225 58.928,22.225 60.198,20.955 60.198,5.207 58.928,3.937
NetC1_1 on Top Layer "TOP_LAYER_NETC1_1_P014" (solid, remove dead copper, pour order 14): 48.557,23.114 48.049,23.622 48.049,32.131 48.049,35.052 50.843,37.846 50.843,44.366 51.816,45.339 59.309,45.339 60.198,44.45 60.198,24.511 58.801,23.114
NetC1_2 on Top Layer "TOP_LAYER_NETC1_2_P016" (solid, remove dead copper, pour order 16): 50.335,38.354 49.7,37.719 46.271,37.719 45.636,38.354 45.636,40.513 46.144,41.021 49.7,41.021 50.335,40.386 50.335,40.259
GND2 on Top Layer "TOP_LAYER_GND2_P020" (solid, remove dead copper, pour order 20): 47.541,30.306 47.541,18.542 47.033,18.034 46.779,17.78 46.779,3.937 36.746,3.937 31.775,8.908 31.775,27.287 35.095,30.607 47.24,30.607
NetD2_2 on Top Layer "TOP_LAYER_NETD2_2_P022" (solid, remove dead copper, pour order 22): 27.686,31.369 22.388,31.369 cw(c22.388,33.909) 20.592,32.113 20.32,32.385 ccw(c18.695,30.76) 18.695,33.058 18.542,33.058 17.615,33.058 cw(c17.615,33.909) 16.764,33.909 16.764,35.433 ccw(c15.748,35.433) 15.748,36.449 15.24,36.449 cw(c15.24,37.465) 14.224,37.465 14.224,44.323 cw(c15.24,44.323) 15.24,45.339 28.194,45.339 cw(c28.194,44.196) 29.337,44.196 29.337,32.512 cw(c28.194,32.512) 28.194,31.369
NetC2_1 on Top Layer "TOP_LAYER_NETC2_1_P024" (solid, remove dead copper, pour order 24): 16.891,3.81 26.416,3.81 29.337,6.731 29.337,29.972 28.702,30.607 20.828,30.607 19.685,29.464 13.335,29.464 13.082,29.464 12.701,29.083 12.701,27.558 13.208,27.051 16.002,27.051 16.764,26.289 16.764,19.05 16.764,3.937 16.891,3.81
NetD1_2 on Top Layer "TOP_LAYER_NETD1_2_P026" (solid, remove dead copper, pour order 26): 43.942,31.369 33.528,31.369 cw(c33.528,33.147) 31.75,33.147 31.75,43.815 cw(c33.274,43.815) 33.274,45.339 43.18,45.339 cw(c43.18,43.815) 44.704,43.815 44.704,32.131 cw(c43.942,32.131)
GND on Bottom Layer "BOTTOM_LAYER_GND_P028" (solid, remove dead copper, pour order 28): 29.337,1.524 29.337,45.212 29.21,45.339 5.588,45.339 1.143,40.894 1.143,1.524
GND2 on Bottom Layer "BOTTOM_LAYER_GND2_P030" (solid, remove dead copper, pour order 30): 31.75,1.524 31.75,27.262 35.095,30.607 60.198,30.607 60.198,1.524

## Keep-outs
Keep-Out Layer:
  text ".Layer_Name" at 14.656,-21.806 h1.52

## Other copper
Top Layer:
  text ".Layer_Name" at 14.656,-21.806 h1.52
Bottom Layer:
  text ".Layer_Name" at 14.656,-21.806 h1.52

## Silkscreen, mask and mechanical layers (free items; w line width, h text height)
Top Overlay:
  text "VOUT" at 46.736,21.717 h0.9 r90
  text "GND" at 41.148,13.716 h0.9 r90
  text "TPS40210 Flyback" at 61.722,6.477 h0.8 r90
  text "VIN" at 23.495,1.27 h1
  text "VOUT" at 52.197,1.27 h1
  text "5/2017" at 61.722,0.508 h0.8 r90
  text ".Layer_Name" at 14.656,-21.806 h1.52
Bottom Overlay:
  text ".PCB_Rev" at 30.226,42.545 h3.05
  text ".PRJ_Number" at 58.928,42.545 h3.05
  text ".Layer_Name" at 14.656,-21.806 h1.52
Top Paste:
  text ".Layer_Name" at 14.656,-21.806 h1.52
Bottom Paste:
  text ".Layer_Name" at 14.656,-21.806 h1.52
Top Solder:
  rectangle: 8.998,26.416 10.965,28.097
  text "'.PCB_Rev'" at 2.921,20.32 h1.2 r90
  text "'.PRJ_Number'" at 2.921,9.906 h1.2 r90
  text ".Layer_Name" at 14.656,-21.806 h1.52
  text ".Layer_Name" at 14.656,-21.806 h1.52
Bottom Solder:
  text ".Layer_Name" at 14.656,-21.806 h1.52
Drill Guide:
  text ".Layer_Name" at 14.656,-21.806 h1.52
M1 Board Outline:
  the board outline again, w0.254
  text ".Layer_Name" at 14.656,-21.806 h1.52
M2 Board Dimensions:
  rectangle: 0,-6.985 3.175,-3.81
  rectangle: 3.175,-10.16 12.7,-6.985
  lines w0.178: 0,-6.985 25.4,-6.985 ; 3.175,-10.16 3.175,-3.81 ; 6.35,-10.16 6.35,-3.81 ; 12.7,-10.16 12.7,-3.81 ; 19.05,-10.16 19.05,-3.81 ; 0,-10.16 25.4,-10.16 25.4,-3.81 0,-3.81 0,-10.16
  text "'.Print_Date'" at 1.651,48.26 h3
  text "'.Print_Time'" at 33.655,48.26 h3
  text ".Layer_Name" at 14.656,-21.806 h1.52
M3 3D STEP Top:
  text ".Layer_Name" at 14.656,-21.806 h1.52
M4 3D STEP Bottom:
  text ".Layer_Name" at 14.656,-21.806 h1.52
M5 Assembly Top:
  lines w0.254: -7.417,-23.626 160.223,-23.626 ; -7.417,-18.462 160.274,-18.462 ; -7.417,-13.297 -7.417,-28.791 94.31,-28.791 160.274,-28.791 160.274,-13.297 -7.404,-13.297 -7.404,-28.791 32.614,-28.791 ; 55.194,-28.791 55.194,-13.297 ; 87.376,-18.462 87.376,-13.297 ; 108.712,-18.462 108.712,-13.297 ; 124.511,-28.956 124.511,-23.804
  text "COMPONENTS MARKED 'DNP' SHOULD NOT BE POPULATED." at 29.299,-8.09 h1.52
  text "ASSEMBLY VARIANT:" at 29.286,-11.024 h1.52
  text ".VariantName" at 55.601,-11.024 h1.52
  text "PCB VIEWED FROM TOP SIDE" at -5.804,-16.654 h1.52
  text "BOARD #:" at 57.099,-16.654 h1.52
  text ".PRJ_Number" at 70.955,-16.654 h1.52
  text "REV:" at 92.405,-16.654 h1.52
  text ".PCB_Rev" at 99.809,-16.654 h1.52
  text "SVN REV:" at 113.69,-16.654 h1.52
  text ".VersionControl_RevNumber" at 126.543,-16.654 h1.52
  text "TID #:" at 57.099,-21.819 h1.52
  text ".TID" at 70.955,-21.819 h1.52
  text "PLOT NAME =" at -5.804,-27.034 h1.52
  text ".plot_File_Name" at 14.656,-27.034 h1.52
  text "GENERATED    :" at 57.15,-27.034 h1.52
  text ".Print_Date" at 79.235,-27.034 h1.52
  text ".Print_Time" at 97.752,-27.034 h1.52
  text "TEXAS INSTRUMENTS" at 129.87,-27.034 h1.52
M6 Assembly Bottom:
  lines w0.254: -7.429,-18.474 160.261,-18.474 ; -7.379,-23.639 160.261,-23.639 ; 28.334,-28.969 28.334,-23.817 ; 44.133,-18.474 44.133,-13.31 ; 65.468,-18.474 65.468,-13.31 ; 97.65,-28.804 97.65,-13.31 ; 120.231,-28.804 160.249,-28.804 160.249,-13.31 -7.429,-13.31 -7.429,-28.804 58.534,-28.804 160.261,-28.804 160.261,-13.31
  text "COMPONENTS MARKED 'DNP' SHOULD NOT BE POPULATED." at 154.991,-8.077 h1.52
  text ".VariantName" at 128.473,-11.024 h1.52
  text "ASSEMBLY VARIANT:" at 154.864,-11.024 h1.52
  text ".VersionControl_RevNumber" at 26.302,-16.667 h1.52
  text "SVN REV:" at 39.154,-16.667 h1.52
  text ".PCB_Rev" at 53.035,-16.667 h1.52
  text "REV:" at 60.439,-16.667 h1.52
  text ".PRJ_Number" at 81.89,-16.667 h1.52
  text "BOARD #:" at 95.745,-16.667 h1.52
  text "PCB VIEWED FROM BOTTOM SIDE" at 158.648,-16.667 h1.52
  text ".TID" at 81.89,-21.831 h1.52
  text "TID #:" at 95.745,-21.831 h1.52
  text "TEXAS INSTRUMENTS" at 22.974,-27.047 h1.52
  text ".Print_Time" at 55.093,-27.047 h1.52
  text ".Print_Date" at 73.609,-27.047 h1.52
  text "GENERATED    :" at 95.694,-27.047 h1.52
  text ".plot_File_Name" at 138.189,-27.047 h1.52
  text "PLOT NAME =" at 158.648,-27.047 h1.52
M9 Title Sheet:
  drawing of 57 lines, arcs and shapes, not listed
  text "1" at 18.792,204.127 h1.78
  text "2" at 82.182,204.127 h1.78
  text "3" at 145.411,204.127 h1.78
  text "4" at 209.08,204.127 h1.78
  text "5" at 272.555,204.127 h1.78
  text "6" at 336.182,204.127 h1.78
  text "A" at -10.579,175.095 h1.78
  text "A" at 365.341,175.095 h1.78
  text "B" at -10.579,114.643 h1.78
  text "B" at 365.341,114.643 h1.78
  text "C" at -10.579,54.318 h1.78
  text "C" at 365.341,54.318 h1.78
  text "PROJECT TITLE:" at 288.125,7.048 h1.14
  text ".PRJ_Title" at 289.395,3.662 h1.78
  text "DESIGNED FOR:" at 288.125,-0.597 h1.14
  text ".PRJ_Customer" at 289.395,-4.153 h1.78
  text "D" at -10.579,-5.88 h1.78
  text "D" at 365.341,-5.88 h1.78
  text "FILE NAME:" at 288.125,-8.217 h1.14
  text ".PCB_File_Name_No_Path" at 289.395,-11.265 h1.78
  text "Texas Instruments (TI) and/or its licensors do not warrant the accuracy or completeness of this specification" at 161.9,-15.376 h1.14
  text "ENGINEER:" at 288.125,-15.583 h1.14
  text "LAYOUT BY:" at 326.352,-15.583 h1.14
  text "or any information contained therein. TI and/or its licensors do not warrant that this design will meet" at 160.757,-18.237 h1.14
  text ".PRJ_Engineer" at 289.395,-19.52 h1.78
  text ".PCB_Layout" at 327.635,-19.52 h1.78
  text "the specifications, will be suitable for your application or fit for any particular purpose, or will operate in" at 160.757,-21.099 h1.14
  text ".Layer_Name" at 14.656,-21.806 h1.52
  text "ALTIUM DESIGNER VERSION:" at 326.352,-23.457 h1.14
  text "an implementation. TI and/or its licensors do not warrant that the design is production worthy. You should" at 160.757,-23.961 h1.14
  text "completely validate and test your design implementation to confirm the system functionality for your application." at 161.9,-26.822 h1.14
  text ".print_Scale" at 289.395,-26.843 h1.78
  text ".Application_BuildNumber" at 327.635,-26.843 h1.78
  text "1" at 18.792,-32.093 h1.78
  text "2" at 82.182,-32.093 h1.78
  text "3" at 145.411,-32.093 h1.78
  text "4" at 209.08,-32.093 h1.78
  text "5" at 272.555,-32.093 h1.78
  text "6" at 336.182,-32.093 h1.78
M10 Fab Notes:
  drawing of 173 lines, arcs and shapes, not listed
  text "DESIGN INFORMATION" at 314.402,157.505 h1.52
  text "MIN. TRACK WIDTH:" at 298.03,152.933 h1.52
  text "8" at 325.874,152.933 h1.52
  text "MIL" at 329.805,152.933 h1.52
  text "MIN. CLEARANCE:" at 298.03,149.581 h1.52
  text "0.2" at 324.35,149.581 h1.52
  text "mm" at 329.805,149.581 h1.52
  text "MIN. VIA PAD SIZE:" at 298.03,146.228 h1.52
  text "24" at 325.113,146.228 h1.52
  text "MIL" at 329.805,146.228 h1.52
  text "0.05mm (2MIL)" at 315.683,142.628 h1.52
  text "MINIMUM ANNULAR RING" at 289.667,142.52 h1.52
  text "EXTERNAL" at 333.666,142.52 h1.52
  text "PER" at 294.747,139.522 h1.52
  text "IPC-D-275 CLASS 2 LEVEL C" at 300.335,139.522 h1.52
  text "MIL, HOLES" at 338.136,136.67 h1.52
  text "+/-" at 328.168,136.652 h1.52
  text "+/-" at 349.86,136.652 h1.52
  text "REGISTRATION TOLERANCES:" at 289.667,136.525 h1.52
  text "METAL" at 320.142,136.525 h1.52
  text "5" at 334.777,136.525 h1.52
  text "3" at 355.935,136.525 h1.52
  text "MIL" at 358.888,136.525 h1.52
  text "+/-" at 349.86,133.655 h1.52
  text "HOLE SIZE TOLERANCE (UNLESS OTHERWISE SPECIFIED):" at 289.667,133.528 h1.52
  text "3" at 355.935,133.528 h1.52
  text "MIL" at 358.888,133.528 h1.52
  text "MATERIAL:" at 287.768,128.208 h1.52
  text "FR-4 High Tg" at 312.824,124.643 h1.52
  text "FR-408" at 298.462,124.425 h1.52
  text "OTHER" at 336.257,124.425 h1.52
  text "X" at 308.889,124.333 h1.52
  text "62 MIL (1.6mm) +/-10%" at 306.592,120.292 h1.52
  text "THICKNESS:" at 289.667,120.184 h1.52
  text "X" at 303.337,120.184 h1.52
  text "OTHER" at 339.229,120.184 h1.52
  text "TOLERANCE:" at 289.667,116.17 h1.52
  text "X" at 310.986,116.17 h1.52
  text "ANSI IPC-6012 TYPE 3 CLASS 2" at 315.734,116.17 h1.52
  text "OTHER +/-" at 315.734,112.208 h1.52
  text "BOW & TWIST:" at 289.667,108.22 h1.52
  text "X" at 310.986,108.22 h1.52
  text "ANSI IPC-6012 TYPE 3 CLASS 2" at 315.734,108.22 h1.52
  text "OTHER +/-" at 315.734,104.194 h1.52
  text "DRILLING:" at 287.768,100.676 h1.52
  text "REFERENCE:" at 289.667,97.705 h1.52
  text "X" at 306.132,97.705 h1.52
  text "AS SHOWN" at 310.882,97.705 h1.52
  text "X" at 329.018,97.705 h1.52
  text "NC_DRILL FILES" at 332.498,97.705 h1.52
  text "PTH MIN COPPER THICKNESS:" at 289.667,93.691 h1.52
  text "X" at 323.963,93.691 h1.52
  text "1MIL" at 327.443,93.691 h1.52
  text "OTHER" at 340.067,93.691 h1.52
  text "BOARD FINISH:" at 287.768,89.653 h1.52
  text "SILKSCREEN:" at 291.711,86.656 h1.52
  text "X" at 315.81,86.656 h1.52
  text "TOP" at 319.01,86.656 h1.52
  text "X" at 328.764,86.656 h1.52
  text "BOTTOM" at 331.99,86.656 h1.52
  text "SILKSCREEN COLOR:" at 291.711,82.414 h1.52
  text "X" at 315.783,82.414 h1.52
  text "WHITE" at 319.01,82.414 h1.52
  text "OTHER" at 331.99,82.414 h1.52
  text "X" at 319.111,78.37 h1.52
  text "GREEN" at 322.338,78.37 h1.52
  text "OTHER" at 338.035,78.37 h1.52
  text "SOLDER RESIST COLOR:" at 291.711,78.096 h1.52
  text "X" at 319.111,74.052 h1.52
  text "MATTE" at 322.338,74.052 h1.52
  text "SEMI-GLOSS" at 338.023,74.036 h1.52
  text "IMMERSION GOLD (ENIG)" at 314.718,69.264 h1.52
  text "ENEPIG" at 348.691,69.18 h1.52
  text "SURFACE FINISH:" at 287.768,69.155 h1.52
  text "X" at 309.969,69.155 h1.52
  text "IMM. TIN/SILVER OR EQUIV" at 296.139,65.167 h1.52
  text "OTHER" at 332.498,65.167 h1.52
  text "ARRAY/PANEL:" at 287.768,60.621 h1.52
  text "CUT AND TRIM PER M1 BOARD OUTLINE" at 314.718,60.512 h1.52
  text "N.C. ROUTE" at 314.718,56.658 h1.52
  text "X" at 331.964,56.658 h1.52
  text "V. SCORE" at 336.714,56.658 h1.52
  text "CERTIFICATION:" at 287.768,53.178 h1.52
  text "MATERIALS AND WORKMANSHIP FOR ALL PCBS" at 306.183,53.178 h1.52
  text "TO MEET OR EXCEED THE REQUIREMENTS OF:" at 306.183,50.689 h1.52
  text "X" at 296.696,47.222 h1.52
  text "ANSI IPC-A-600F CLASS ->" at 300.227,47.222 h1.52
  text "X" at 341.859,47.222 h1.52
  text "2" at 344.88,47.222 h1.52
  text "1" at 336.879,47.184 h1.52
  text "3" at 353.872,47.184 h1.52
  text "X" at 317.373,43.171 h1.52
  text "RoHS" at 320.852,43.171 h1.52
  text "OTHER" at 337.22,43.171 h1.52
  text "PER ORDER" at 347.305,43.171 h1.52
  text "ALL BOARDS MUST MEET OR EXCEED UL94-V0 REQUIREMENTS." at 288.468,38.964 h1.52
  text "PCB MUST BEAR THE UL94V-0 UL REGISTERED MATERIAL ID NUMBER" at 288.468,35.916 h1.52
  text "ADDITIONAL REQUIREMENTS:" at 287.768,31.512 h1.52
  text "MICROSECTION:" at 289.667,28.591 h1.52
  text "YES" at 312.673,28.591 h1.52
  text "REQUIRED" at 334.555,24.625 h1.52
  text "BARE BOARD ELEC. TEST:" at 289.667,24.553 h1.52
  text "NONE" at 322.833,24.553 h1.52
  text "X" at 331.329,24.553 h1.52
  text "PER ORDER" at 349.592,24.553 h1.52
  text ".Layer_Name" at 14.656,-21.806 h1.52
M11 Gerber Information:
  lines w0.254: -7.417,-23.626 160.223,-23.626 ; -7.417,-18.462 160.274,-18.462 ; -7.417,-13.297 -7.417,-28.791 94.31,-28.791 160.274,-28.791 160.274,-13.297 -7.404,-13.297 -7.404,-28.791 32.614,-28.791 ; 55.194,-28.791 55.194,-13.297 ; 87.376,-18.462 87.376,-13.297 ; 108.712,-18.462 108.712,-13.297 ; 124.511,-28.956 124.511,-23.804
  text "ALL ARTWORK VIEWED FROM TOP SIDE" at -5.804,-16.654 h1.52
  text "BOARD #:" at 57.099,-16.654 h1.52
  text ".PRJ_Number" at 70.955,-16.654 h1.52
  text "REV:" at 92.405,-16.654 h1.52
  text ".PCB_Rev" at 99.809,-16.654 h1.52
  text "SVN REV:" at 113.69,-16.654 h1.52
  text ".VersionControl_RevNumber" at 126.543,-16.654 h1.52
  text "LAYER NAME =" at -5.804,-21.806 h1.52
  text "TID #:" at 57.099,-21.819 h1.52
  text ".TID" at 70.955,-21.819 h1.52
  text "PLOT NAME =" at -5.804,-27.034 h1.52
  text ".plot_File_Name" at 14.656,-27.034 h1.52
  text "GENERATED    :" at 57.15,-27.034 h1.52
  text ".Print_Date" at 79.235,-27.034 h1.52
  text ".Print_Time" at 97.752,-27.034 h1.52
  text "TEXAS INSTRUMENTS" at 129.87,-27.034 h1.52
M12 Stackup:
  drawing of 191 lines, arcs and shapes, not listed
  text "Layer" at 248.675,198.882 h1.52
  text "Name" at 259.086,198.882 h1.52
  text "Material" at 282.702,198.882 h1.52
  text "Thickness" at 304.54,198.882 h1.52
  text "Constant" at 321.046,198.882 h1.52
  text "Board Layer Stack" at 335.52,198.882 h1.52
  text "1" at 248.675,195.834 h1.52
  text "Top Overlay" at 259.086,195.834 h1.52
  text "2" at 248.675,192.786 h1.52
  text "Top Solder" at 259.086,192.786 h1.52
  text "Solder Resist" at 282.702,192.786 h1.52
  text "0.40mil" at 304.54,192.786 h1.52
  text "3.5" at 321.046,192.786 h1.52
  text "3" at 248.675,189.738 h1.52
  text "Top Layer" at 259.086,189.738 h1.52
  text "Copper" at 282.702,189.738 h1.52
  text "1.40mil" at 304.54,189.738 h1.52
  text "4" at 248.675,186.69 h1.52
  text "Dielectric1" at 259.086,186.69 h1.52
  text "FR-4" at 282.702,186.69 h1.52
  text "59.20mil" at 304.54,186.69 h1.52
  text "4.8" at 321.046,186.69 h1.52
  text "5" at 248.675,183.642 h1.52
  text "Bottom Layer" at 259.086,183.642 h1.52
  text "Copper" at 282.702,183.642 h1.52
  text "1.40mil" at 304.54,183.642 h1.52
  text "6" at 248.675,180.594 h1.52
  text "Bottom Solder" at 259.086,180.594 h1.52
  text "Solder Resist" at 282.702,180.594 h1.52
  text "0.40mil" at 304.54,180.594 h1.52
  text "3.5" at 321.046,180.594 h1.52
  text "7" at 248.675,177.546 h1.52
  text "Bottom Overlay" at 259.086,177.546 h1.52
  text ".Layer_Name" at 14.656,-21.806 h1.52
M13 Component Bodies Top:
  text ".Layer_Name" at 14.656,-21.806 h1.52
M14 Component Bodies Bottom:
  text ".Layer_Name" at 14.656,-21.806 h1.52
M15 Courtyards Top:
  text ".Layer_Name" at 14.656,-21.806 h1.52
M16 Courtyards Bottom:
  text ".Layer_Name" at 14.656,-21.806 h1.52
Drill Drawing:
  lines w0.254: 135.538,72.767 136.944,72.767 136.944,74.173 135.538,74.173 135.538,72.767 ; 135.538,77.335 136.944,77.335 136.241,75.929 135.538,77.335 ; 135.538,79.092 136.241,79.443 136.944,79.092 136.593,79.795 136.944,80.497 136.241,80.146 135.538,80.497 135.89,79.795 135.538,79.092 ; 135.538,82.605 135.89,82.605 135.89,82.254 136.593,82.254 136.593,82.605 136.944,82.605 136.944,83.308 136.593,83.308 136.593,83.66 135.89,83.66 135.89,83.308 135.538,83.308 135.538,82.605
  lines w0.305: 134.264,71.819 212.445,71.819 ; 134.264,84.468 212.445,84.468 ; 142.85,68.656 142.85,87.63 ; 151.287,68.656 151.287,87.63 ; 167.453,68.656 167.453,87.63 ; 174.037,68.656 174.037,87.63 ; 183.568,68.656 183.568,87.63 ; 201.972,68.656 201.972,87.63 ; 134.264,68.656 212.445,68.656 212.445,87.63 134.264,87.63 134.264,68.656
  text "Symbol" at 136.162,85.416 h1.83
  text "Quantity" at 143.799,85.416 h1.83
  text "Finished Hole Size" at 152.235,85.416 h1.83
  text "Plated" at 168.402,85.416 h1.83
  text "Hole Type" at 174.986,85.416 h1.83
  text "Drill Layer Pair" at 184.517,85.416 h1.83
  text "Tolerance" at 202.92,85.416 h1.83
  text "17" at 143.799,82.254 h1.52
  text "11.81mil (0.300mm)" at 152.235,82.254 h1.52
  text "PTH" at 168.402,82.254 h1.52
  text "Round" at 174.986,82.254 h1.52
  text "Top Layer - Bottom Layer" at 184.517,82.254 h1.52
  text "18" at 143.799,79.092 h1.52
  text "19.69mil (0.500mm)" at 152.235,79.092 h1.52
  text "PTH" at 168.402,79.092 h1.52
  text "Round" at 174.986,79.092 h1.52
  text "Top Layer - Bottom Layer" at 184.517,79.092 h1.52
  text "9" at 143.799,75.929 h1.52
  text "40.00mil (1.016mm)" at 152.235,75.929 h1.52
  text "PTH" at 168.402,75.929 h1.52
  text "Round" at 174.986,75.929 h1.52
  text "Top Layer - Bottom Layer" at 184.517,75.929 h1.52
  text "4" at 143.799,72.767 h1.52
  text "50.00mil (1.270mm)" at 152.235,72.767 h1.52
  text "PTH" at 168.402,72.767 h1.52
  text "Round" at 174.986,72.767 h1.52
  text "Top Layer - Bottom Layer" at 184.517,72.767 h1.52
  text "48 Total" at 143.799,69.605 h1.52
  text ".Layer_Name" at 14.656,-21.806 h1.52

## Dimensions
0,-10.16 to 25.4,-10.16 on M2 Board Dimensions
0,0 to 0,46.99 on M2 Board Dimensions
0,0 to 62.23,0 on M2 Board Dimensions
